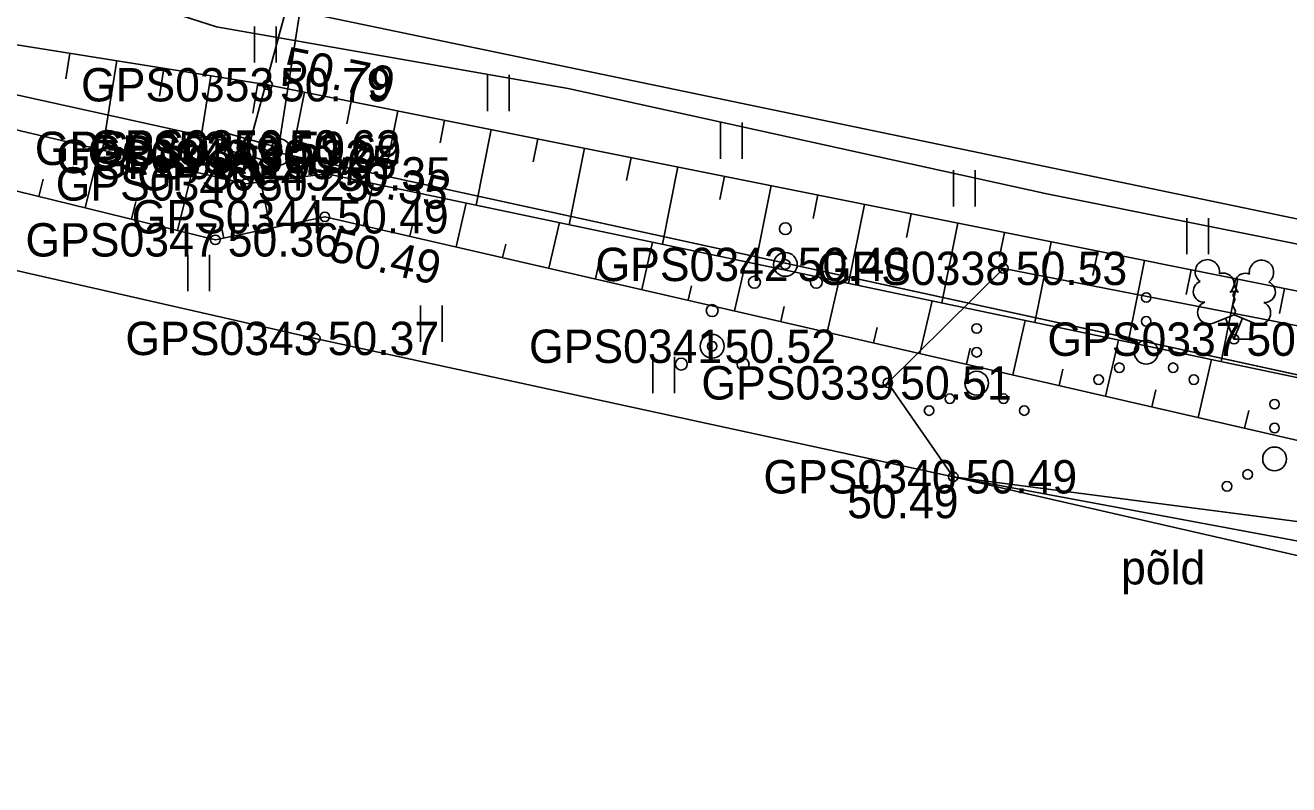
# Model space of a CAD drawing. Extents: x 551623 to 559850, y 6561220 to 6567135.
# Drawn here: x 555686.72 to 555713.27, y 6565365.32 to 6565381.27 of the extents above; entities that cross this region are included whole.
import ezdxf

# ---------------------------------------------------------------- set-up
doc = ezdxf.new("R2010")
doc.units = 0
for name, color, linetype in [('HALJASTUS', 7, 'Continuous'), ('KORGUS-EH2000', 7, 'Continuous'), ('MOOTKORG-EH2000', 7, 'Continuous'), ('MOOTMPUNKT', 7, 'Continuous'), ('MOOTNR', 7, 'Continuous'), ('MOOTPIIR', 7, 'Continuous'), ('MPKAABEL', 7, 'Continuous'), ('PIIR', 7, 'Continuous'), ('PIIRIMLEITUD', 7, 'Continuous'), ('PUU', 7, 'Continuous'), ('RELJEEF', 7, 'Continuous'), ('TEE', 7, 'Continuous'), ('TRUUP', 7, 'Continuous')]:
    doc.layers.add(name, color=color, linetype=linetype)

msp = doc.modelspace()

# ---------------------------------------------------------------- linework, layer by layer
at = {"layer": 'HALJASTUS'}
for p, q in [((555691.538, 6565381.249), (555691.538, 6565380.488)), ((555691.993, 6565381.249), (555691.993, 6565380.488)), ((555696.433, 6565380.228), (555696.433, 6565379.467)), ((555696.888, 6565380.228), (555696.888, 6565379.467)), ((555701.332, 6565379.227), (555701.332, 6565378.466)), ((555701.787, 6565379.227), (555701.787, 6565378.466)), ((555706.23, 6565378.226), (555706.23, 6565377.464)), ((555706.685, 6565378.226), (555706.685, 6565377.464)), ((555711.129, 6565377.224), (555711.129, 6565376.463)), ((555711.584, 6565377.224), (555711.584, 6565376.463)), ((555690.138, 6565376.448), (555690.138, 6565375.687)), ((555690.593, 6565376.448), (555690.593, 6565375.687)), ((555695.024, 6565375.384), (555695.024, 6565374.623)), ((555695.479, 6565375.384), (555695.479, 6565374.623)), ((555699.907, 6565374.309), (555699.907, 6565373.548)), ((555700.362, 6565374.309), (555700.362, 6565373.548))]:
    msp.add_line(p, q, dxfattribs=at)
for points in [[(555675.68, 6565378.588), (555692.816, 6565374.696), (555706.223, 6565371.79), (555718.659, 6565369.474), (555736.594, 6565365.263), (555739.63, 6565364.32), (555744.313, 6565362.373)], [(555706.223, 6565371.79), (555704.848, 6565373.763), (555707.275, 6565376.167), (555718.171, 6565374.046), (555719.566, 6565372.024), (555717.604, 6565370.312), (555706.223, 6565371.79)]]:
    msp.add_lwpolyline(points, dxfattribs=at)
for centre, radius in [((555710.277, 6565375.555), 0.1), ((555710.277, 6565375.055), 0.1), ((555706.714, 6565374.905), 0.1), ((555710.277, 6565374.405), 0.25), ((555706.714, 6565374.405), 0.1), ((555709.712, 6565374.08), 0.1), ((555710.842, 6565374.08), 0.1), ((555706.714, 6565373.755), 0.25), ((555709.277, 6565373.83), 0.1), ((555711.277, 6565373.83), 0.1), ((555706.149, 6565373.43), 0.1), ((555707.279, 6565373.43), 0.1), ((555705.714, 6565373.18), 0.1), ((555707.714, 6565373.18), 0.1), ((555712.974, 6565373.315), 0.1), ((555712.974, 6565372.815), 0.1), ((555712.974, 6565372.165), 0.25), ((555712.409, 6565371.84), 0.1), ((555711.974, 6565371.59), 0.1)]:
    msp.add_circle(centre, radius, dxfattribs=at)
at = {"layer": 'KORGUS-EH2000'}
for centre in [(555691.814, 6565380.023), (555693.062, 6565378.152), (555693.017, 6565377.25), (555692.816, 6565374.696), (555706.223, 6565371.79)]:
    msp.add_circle(centre, 0.1, dxfattribs=at)
at = {"layer": 'MOOTMPUNKT'}
for centre in [(555691.814, 6565380.023), (555690.843, 6565378.687), (555692.005, 6565378.717), (555691.363, 6565378.517), (555692.022, 6565378.614), (555691.92, 6565378.391), (555691.351, 6565377.94), (555693.062, 6565378.152), (555693.017, 6565377.25), (555690.716, 6565376.766), (555702.694, 6565376.25), (555707.275, 6565376.167), (555692.816, 6565374.696), (555701.156, 6565374.531), (555712.121, 6565374.68), (555704.848, 6565373.763), (555706.223, 6565371.79)]:
    msp.add_circle(centre, 0.1, dxfattribs=at)
at = {"layer": 'MOOTPIIR'}
msp.add_lwpolyline([(555497.95, 6565427.828), (555519.263, 6565422.564), (555542.613, 6565417.073), (555565.599, 6565412.035), (555589.51, 6565406.357), (555610.656, 6565401.422), (555635.154, 6565395.619), (555656.789, 6565389.809), (555677.01, 6565385.399), (555676.796, 6565382.423), (555676.325, 6565380.291), (555675.68, 6565378.588), (555692.816, 6565374.696), (555706.223, 6565371.79), (555756.448, 6565360.308), (555766.29, 6565358.132), (555785.422, 6565354.502), (555797.457, 6565355.318), (555821.88, 6565355.238), (555839.435, 6565355.215), (555871.496, 6565354.829)], dxfattribs=at)
at = {"layer": 'MPKAABEL'}
msp.add_lwpolyline([(555754.809, 6565368.578), (555745.82, 6565370.031), (555736.449, 6565371.941), (555727.141, 6565373.859), (555717.551, 6565375.859), (555708.191, 6565377.73), (555698.129, 6565379.941), (555690.738, 6565381.238), (555690.039, 6565381.461), (555689.559, 6565381.898), (555690.18, 6565387.07), (555689.871, 6565387.539), (555689.309, 6565387.75), (555680.781, 6565389.43), (555671.469, 6565391.391), (555661.898, 6565393.719)], dxfattribs=at)
at = {"layer": 'PIIR'}
for points in [[(555693.4, 6565387.37), (555722.09, 6565569.1), (555756.75, 6565564.43), (555823.05, 6565554.69), (555792.17, 6565359.86), (555785.15, 6565359.9), (555766.77, 6565362.31), (555692.03, 6565378.6)], [(555443.35, 6565442.49), (555368.05, 6565461.11), (555419.74, 6565450.66), (555470.4, 6565439.4), (555495.41, 6565433.85), (555584.65, 6565412.91), (555693.4, 6565387.37), (555692.03, 6565378.6), (555540.46, 6565411.94), (555441.38, 6565433.61)]]:
    msp.add_lwpolyline(points, close=True, dxfattribs=at)
msp.add_lwpolyline([(555499.25, 6565219.2), (555540.46, 6565411.94), (555692.03, 6565378.6), (555766.77, 6565362.31), (555867.36, 6565030.76), (555870.22, 6565021.13), (555863.3, 6565012.86), (555851.12, 6564995.46), (555840.86, 6564982.81), (555830.44, 6564972.56), (555821.06, 6564966.89), (555810.6, 6564964.68), (555800.15, 6564967.91), (555790.22, 6564974.7), (555774.12, 6564982.77), (555764.52, 6564984.31), (555761.21, 6564983.07), (555750.61, 6564983.35), (555554.63, 6564988.6), (555394.15, 6564993.09)], dxfattribs=at)
at = {"layer": 'PIIRIMLEITUD'}
msp.add_circle((555692.022, 6565378.614), 0.285, dxfattribs=at)
at = {"layer": 'PUU'}
for p, q in [((555711.681, 6565375.015), (555712.126, 6565375.19)), ((555712.121, 6565374.68), (555711.946, 6565375.12)), ((555712.121, 6565374.68), (555712.301, 6565375.12)), ((555712.126, 6565375.19), (555712.566, 6565375.01)), ((555712.501, 6565374.68), (555712.121, 6565374.68))]:
    msp.add_line(p, q, dxfattribs=at)
msp.add_lwpolyline([(555712.126, 6565375.685), (555712.106, 6565375.61), (555712.106, 6565375.59), (555712.116, 6565375.56), (555712.136, 6565375.525), (555712.141, 6565375.505), (555712.126, 6565375.47), (555712.101, 6565375.42), (555712.096, 6565375.395), (555712.101, 6565375.38), (555712.111, 6565375.35), (555712.146, 6565375.29), (555712.151, 6565375.27), (555712.146, 6565375.25), (555712.131, 6565375.215), (555712.126, 6565375.19)], dxfattribs=at)
for centre, radius in [((555702.694, 6565377), 0.125), ((555702.694, 6565376.25), 0.25), ((555702.044, 6565375.875), 0.125), ((555703.344, 6565375.875), 0.125), ((555701.156, 6565375.281), 0.125), ((555701.156, 6565374.531), 0.25), ((555700.506, 6565374.156), 0.125), ((555701.806, 6565374.156), 0.125)]:
    msp.add_circle(centre, radius, dxfattribs=at)
for centre, radius, start, end in [((555711.563, 6565376.094), 0.256, 111.5027, 232.5173), ((555711.563, 6565376.094), 0.256, 350.4856, 111.5002), ((555712.699, 6565376.085), 0.256, 67.6168, 188.6314), ((555712.699, 6565376.085), 0.256, 306.5997, 67.6143), ((555711.49, 6565375.682), 0.224, 111.4304, 274.4987), ((555711.898, 6565375.843), 0.224, 308.5041, 111.5725), ((555712.361, 6565375.839), 0.225, 67.7016, 230.5126), ((555712.767, 6565375.673), 0.224, 264.6183, 67.6866), ((555712.125, 6565375.447), 0.237, 66.7655, 111.5015), ((555711.594, 6565375.238), 0.237, 111.5014, 291.5004), ((555712.655, 6565375.23), 0.237, 247.6166, 67.6155)]:
    msp.add_arc(centre, radius, start, end, dxfattribs=at)
at = {"layer": 'RELJEEF'}
for p, q in [((555687.658, 6565380.687), (555687.571, 6565380.144)), ((555688.645, 6565380.529), (555688.345, 6565378.648)), ((555689.633, 6565380.371), (555689.539, 6565379.785)), ((555690.62, 6565380.213), (555690.297, 6565378.189)), ((555691.608, 6565380.056), (555691.507, 6565379.427)), ((555692.59, 6565379.867), (555692.226, 6565378.048)), ((555693.57, 6565379.671), (555693.477, 6565379.203)), ((555694.551, 6565379.475), (555694.237, 6565377.905)), ((555695.531, 6565379.278), (555695.437, 6565378.805)), ((555696.512, 6565379.082), (555696.194, 6565377.494)), ((555697.492, 6565378.886), (555697.397, 6565378.407)), ((555687.98, 6565377.436), (555688.281, 6565378.663)), ((555698.473, 6565378.689), (555698.152, 6565377.084)), ((555699.454, 6565378.493), (555699.357, 6565378.009)), ((555700.434, 6565378.297), (555700.109, 6565376.673)), ((555687.009, 6565377.674), (555687.098, 6565378.04)), ((555689.923, 6565376.96), (555690.228, 6565378.205)), ((555701.415, 6565378.1), (555701.317, 6565377.61)), ((555691.874, 6565377.01), (555691.67, 6565377.98)), ((555693.828, 6565377.064), (555694.031, 6565377.948)), ((555702.395, 6565377.904), (555702.066, 6565376.262)), ((555688.952, 6565377.198), (555689.042, 6565377.569)), ((555692.853, 6565377.215), (555692.797, 6565377.482)), ((555695.777, 6565376.616), (555695.989, 6565377.537)), ((555703.376, 6565377.708), (555703.277, 6565377.212)), ((555704.356, 6565377.511), (555704.024, 6565375.851)), ((555690.895, 6565376.804), (555690.813, 6565377.196)), ((555705.337, 6565377.315), (555705.237, 6565376.814)), ((555694.803, 6565376.84), (555694.865, 6565377.111)), ((555697.726, 6565376.168), (555697.947, 6565377.127)), ((555706.317, 6565377.119), (555705.981, 6565375.44)), ((555696.752, 6565376.392), (555696.817, 6565376.674)), ((555699.675, 6565375.72), (555699.904, 6565376.716)), ((555707.298, 6565376.922), (555707.197, 6565376.416)), ((555708.278, 6565376.726), (555707.939, 6565375.029)), ((555709.259, 6565376.53), (555709.157, 6565376.018)), ((555698.701, 6565375.944), (555698.768, 6565376.237)), ((555701.625, 6565375.272), (555701.862, 6565376.305)), ((555710.239, 6565376.333), (555709.896, 6565374.619)), ((555711.22, 6565376.137), (555711.116, 6565375.62)), ((555703.574, 6565374.824), (555703.82, 6565375.894)), ((555712.201, 6565375.941), (555711.854, 6565374.208)), ((555700.65, 6565375.496), (555700.72, 6565375.8)), ((555713.181, 6565375.744), (555713.076, 6565375.222)), ((555702.599, 6565375.048), (555702.672, 6565375.363)), ((555705.523, 6565374.376), (555705.777, 6565375.483)), ((555707.472, 6565373.928), (555707.735, 6565375.072)), ((555704.548, 6565374.6), (555704.623, 6565374.926)), ((555709.421, 6565373.48), (555709.693, 6565374.661)), ((555706.498, 6565374.152), (555706.575, 6565374.489)), ((555708.447, 6565373.704), (555708.527, 6565374.053)), ((555711.37, 6565373.032), (555711.651, 6565374.25)), ((555710.396, 6565373.256), (555710.479, 6565373.616)), ((555712.345, 6565372.808), (555712.43, 6565373.179))]:
    msp.add_line(p, q, dxfattribs=at)
for points in [[(555676.796, 6565382.423), (555691.814, 6565380.023), (555718.534, 6565374.673), (555737.16, 6565370.78), (555757.791, 6565366.76), (555775.306, 6565363.612), (555775.569, 6565363.481)], [(555676.473, 6565381.443), (555691.351, 6565377.94), (555693.062, 6565378.152), (555718.812, 6565372.747), (555736.993, 6565368.981), (555757.533, 6565364.973), (555774.795, 6565362.737), (555775.176, 6565362.832)], [(555676.325, 6565380.291), (555690.716, 6565376.766), (555693.017, 6565377.25), (555718.583, 6565371.374), (555736.814, 6565367.789), (555756.953, 6565363.922), (555775.175, 6565361.867), (555775.422, 6565362.232)]]:
    msp.add_lwpolyline(points, dxfattribs=at)
at = {"layer": 'TEE'}
msp.add_lwpolyline([(555463.469, 6565434.873), (555479.318, 6565431.962), (555490.115, 6565429.76), (555497.95, 6565427.828), (555519.263, 6565422.564), (555542.613, 6565417.073), (555565.599, 6565412.035), (555589.51, 6565406.357), (555610.656, 6565401.422), (555635.154, 6565395.619), (555656.789, 6565389.809), (555677.01, 6565385.399), (555692.063, 6565381.655), (555718.607, 6565376.133), (555737.61, 6565372.216), (555759.321, 6565368.781), (555773.34, 6565367.27), (555785.196, 6565366.246), (555799.302, 6565365.674), (555824.141, 6565365.476), (555838.654, 6565365.624), (555851.072, 6565365.834)], dxfattribs=at)
at = {"layer": 'TRUUP'}
for p, q in [((555693.875, 6565387.78), (555691.37, 6565378.542)), ((555691.39, 6565378.614), (555690.715, 6565378.227)), ((555691.252, 6565378.371), (555691.243, 6565378.53)), ((555691.276, 6565378.385), (555691.267, 6565378.544)), ((555691.3, 6565378.399), (555691.292, 6565378.558)), ((555691.324, 6565378.413), (555691.316, 6565378.572)), ((555691.35, 6565378.397), (555691.34, 6565378.586)), ((555691.378, 6565378.349), (555691.364, 6565378.6)), ((555691.406, 6565378.3), (555691.389, 6565378.614)), ((555691.777, 6565377.939), (555691.39, 6565378.614)), ((555691.433, 6565378.252), (555691.416, 6565378.568)), ((555691.461, 6565378.204), (555691.444, 6565378.52)), ((555691.363, 6565378.517), (555690.75, 6565378.165)), ((555690.79, 6565378.106), (555690.782, 6565378.266)), ((555691.337, 6565378.42), (555690.785, 6565378.104)), ((555690.814, 6565378.12), (555690.806, 6565378.28)), ((555690.839, 6565378.134), (555690.83, 6565378.294)), ((555690.863, 6565378.148), (555690.854, 6565378.307)), ((555690.887, 6565378.162), (555690.879, 6565378.321)), ((555690.912, 6565378.176), (555690.903, 6565378.335)), ((555690.936, 6565378.19), (555690.927, 6565378.349)), ((555690.96, 6565378.204), (555690.952, 6565378.363)), ((555690.984, 6565378.218), (555690.976, 6565378.377)), ((555691.009, 6565378.232), (555691, 6565378.391)), ((555691.033, 6565378.246), (555691.024, 6565378.405)), ((555691.057, 6565378.26), (555691.049, 6565378.419)), ((555691.082, 6565378.274), (555691.073, 6565378.433)), ((555691.106, 6565378.288), (555691.097, 6565378.447)), ((555691.13, 6565378.301), (555691.122, 6565378.461)), ((555691.154, 6565378.315), (555691.146, 6565378.475)), ((555691.179, 6565378.329), (555691.17, 6565378.488)), ((555691.203, 6565378.343), (555691.194, 6565378.502)), ((555691.227, 6565378.357), (555691.219, 6565378.516)), ((555691.653, 6565377.868), (555691.337, 6565378.42)), ((555691.715, 6565377.904), (555691.363, 6565378.517)), ((555691.489, 6565378.156), (555691.472, 6565378.472)), ((555691.516, 6565378.108), (555691.499, 6565378.424)), ((555691.544, 6565378.059), (555691.527, 6565378.375)), ((555691.571, 6565378.011), (555691.554, 6565378.327)), ((555691.599, 6565377.963), (555691.582, 6565378.279)), ((555690.785, 6565378.104), (555690.715, 6565378.227)), ((555690.736, 6565378.191), (555690.733, 6565378.238)), ((555690.763, 6565378.142), (555690.757, 6565378.252)), ((555691.627, 6565377.915), (555691.61, 6565378.231)), ((555691.654, 6565377.869), (555691.637, 6565378.183)), ((555691.679, 6565377.883), (555691.665, 6565378.134)), ((555691.703, 6565377.897), (555691.693, 6565378.086)), ((555691.727, 6565377.911), (555691.72, 6565378.038)), ((555691.751, 6565377.925), (555691.748, 6565377.99)), ((555691.653, 6565377.868), (555691.777, 6565377.939))]:
    msp.add_line(p, q, dxfattribs=at)
msp.add_lwpolyline([(555690.843, 6565378.687), (555691.92, 6565378.391), (555692.009, 6565378.715), (555690.932, 6565379.012)], close=True, dxfattribs=at)

# ---------------------------------------------------------------- texts
at = {"layer": 'HALJASTUS'}
msp.add_text('põld', height=0.7, dxfattribs=at).set_placement((555709.748, 6565369.53))
at = {"layer": 'KORGUS-EH2000'}
for s, rotation, p in [(' 50.79', 348.6779, (555691.848, 6565380.194)), (' 50.35', 348.1466, (555692.993, 6565377.905)), (' 50.49', 347.0554, (555692.821, 6565376.397))]:
    msp.add_text(s, height=0.7, rotation=rotation, dxfattribs=at).set_placement(p)
for s, p in [(' 50.37', (555692.816, 6565374.346)), (' 50.49', (555703.732, 6565370.92))]:
    msp.add_text(s, height=0.7, dxfattribs=at).set_placement(p)
at = {"layer": 'MOOTKORG-EH2000'}
for s, p in [(' 50.79', (555691.814, 6565379.673)), (' 50.62', (555692.005, 6565378.367)), (' 50.59', (555690.843, 6565378.337)), (' 50.32', (555691.363, 6565378.167)), (' 50.69', (555692.022, 6565378.264)), (' 50.65', (555691.92, 6565378.041)), (' 50.25', (555691.351, 6565377.59)), (' 50.35', (555693.062, 6565377.802)), (' 50.49', (555693.017, 6565376.9)), (' 50.36', (555690.716, 6565376.416)), (' 50.40', (555702.694, 6565375.9)), (' 50.53', (555707.275, 6565375.817)), (' 50.37', (555692.816, 6565374.346)), (' 50.52', (555701.156, 6565374.181)), (' 50.70', (555712.121, 6565374.33)), (' 50.51', (555704.848, 6565373.413)), (' 50.49', (555706.223, 6565371.44))]:
    msp.add_text(s, height=0.7, dxfattribs=at).set_placement(p)
at = {"layer": 'MOOTNR'}
for s, p in [('GPS0353 ', (555687.894, 6565379.673)), ('GPS0350 ', (555688.085, 6565378.367)), ('GPS0352 ', (555686.923, 6565378.337)), ('GPS0348 ', (555687.374, 6565378.167)), ('GPS0349 ', (555688.032, 6565378.264)), ('GPS0351 ', (555688.14, 6565378.041)), ('GPS0346 ', (555687.362, 6565377.59)), ('GPS0345 ', (555689.072, 6565377.802)), ('GPS0344 ', (555688.958, 6565376.9)), ('GPS0347 ', (555686.726, 6565376.416)), ('GPS0342 ', (555698.705, 6565375.9)), ('GPS0338 ', (555703.356, 6565375.817)), ('GPS0343 ', (555688.826, 6565374.346)), ('GPS0341 ', (555697.307, 6565374.181)), ('GPS0337 ', (555708.201, 6565374.33)), ('GPS0339 ', (555700.929, 6565373.413)), ('GPS0340 ', (555702.233, 6565371.44))]:
    msp.add_text(s, height=0.7, dxfattribs=at).set_placement(p)

doc.saveas('drawing.dxf')
